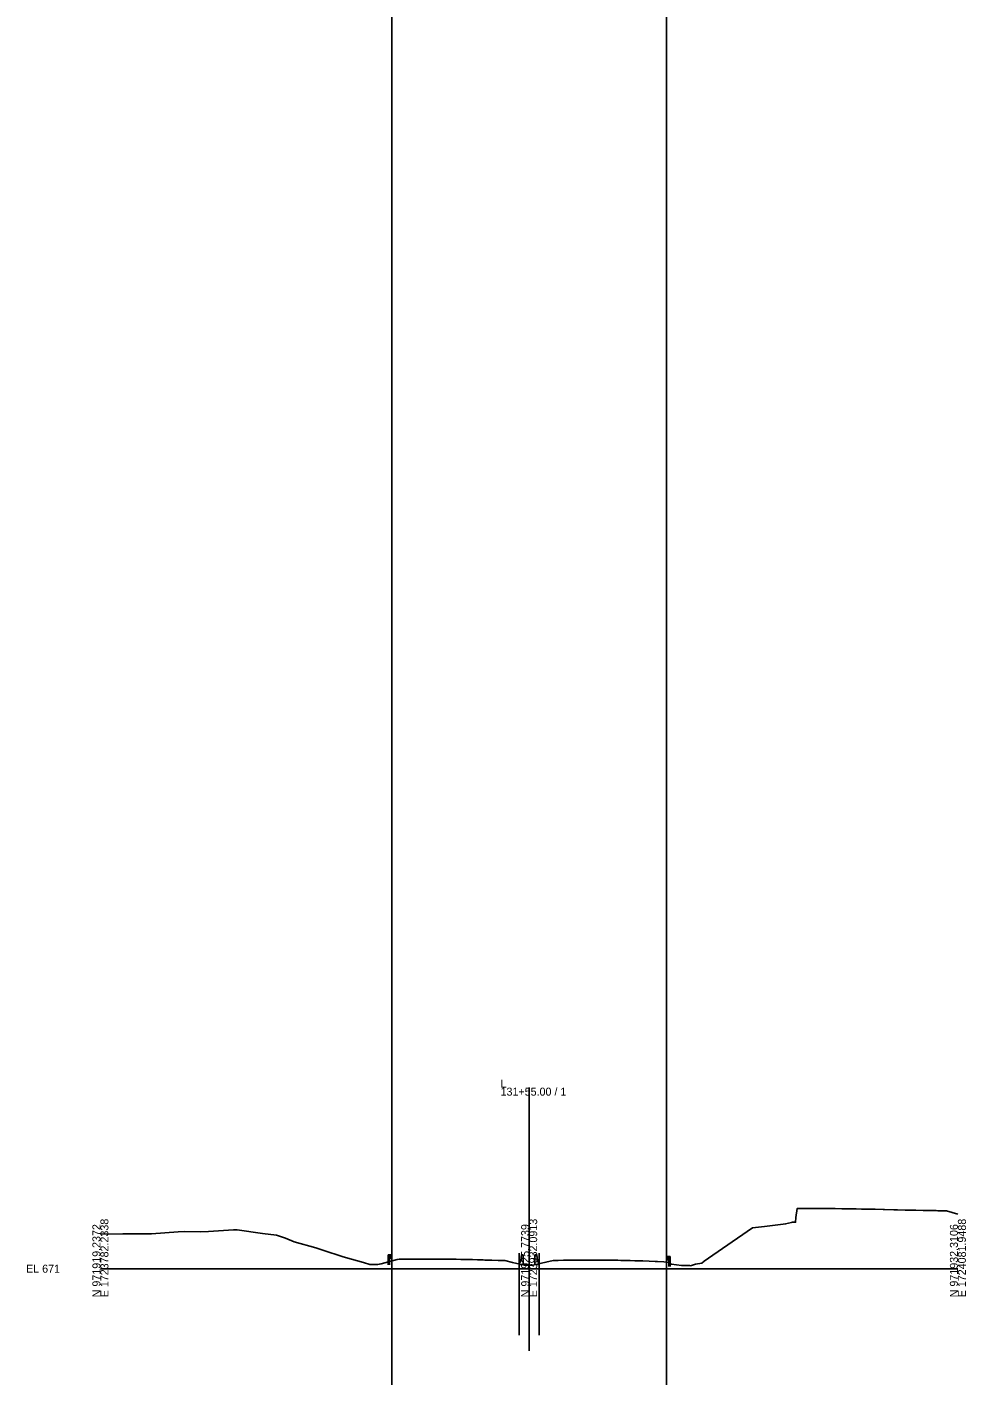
# Model space of a CAD drawing. Extents: x -26 to 303, y -29 to 15026.
# Drawn here: x -25.7 to 302.8, y 4962.8 to 5434.6 of the extents above; entities that cross this region are included whole.
import ezdxf

# ---------------------------------------------------------------- set-up
doc = ezdxf.new("R2010")
doc.units = 0
for name, color, linetype in [('Exist Cross Section Cell', 7, 'Continuous'), ('Exist XS Center Line Elevation Label', 7, 'Continuous'), ('Exist XS Ground Line', 7, 'Continuous'), ('Scratch_Level_0', 7, 'Continuous'), ('Typical Guardrail CELL', 7, 'Continuous'), ('Typical Median Barrier CELL', 7, 'Continuous')]:
    doc.layers.add(name, color=color, linetype=linetype)

msp = doc.modelspace()

# ---------------------------------------------------------------- linework, layer by layer
at = {"layer": 'Exist Cross Section Cell'}
for p, q in [((150, 5000), (150, 5063.37)), ((0, 5000), (150, 5000)), ((150, 5000), (300, 5000))]:
    msp.add_line(p, q, dxfattribs=at)
at = {"layer": 'Exist XS Ground Line'}
msp.add_lwpolyline([(0, 5012.06), (7.79, 5012.2), (8.19, 5012.21), (17.84, 5012.21), (27.19, 5012.94), (29.54, 5013.02), (35.07, 5012.96), (37.81, 5012.97), (46.55, 5013.56), (47.82, 5013.61), (56.69, 5012.3), (61.57, 5011.74), (64.71, 5010.71), (67.84, 5009.46), (75.33, 5007.33), (77.85, 5006.51), (84.92, 5004.14), (87.86, 5003.33), (91.99, 5002.18), (94.31, 5001.47), (94.81, 5001.46), (97.04, 5001.53), (97.57, 5001.55), (98.19, 5001.7), (103.79, 5003.26), (104.55, 5003.29), (105.23, 5003.31), (106.97, 5003.37), (107.79, 5003.38), (109.49, 5003.39), (110.54, 5003.4), (111.24, 5003.4), (111.99, 5003.4), (113.03, 5003.38), (114.49, 5003.37), (115.85, 5003.37), (116.99, 5003.37), (118.25, 5003.35), (119.48, 5003.34), (120.82, 5003.32), (121.96, 5003.31), (122.6, 5003.3), (123.05, 5003.3), (123.71, 5003.3), (124.46, 5003.29), (126.05, 5003.26), (126.96, 5003.25), (128.69, 5003.21), (129.48, 5003.19), (130.21, 5003.17), (131.97, 5003.12), (133.9, 5003.06), (134.48, 5003.05), (134.86, 5003.03), (135.75, 5003.01), (136.97, 5002.96), (139.15, 5002.91), (139.46, 5002.9), (140.41, 5002.87), (141.54, 5002.83), (144.22, 5002.14), (148.28, 5001.29), (150.03, 5001.23), (151.31, 5001.3), (155.84, 5002.28), (158.36, 5002.87), (158.74, 5002.87), (159.53, 5002.89), (160.09, 5002.91), (161.98, 5002.96), (162.8, 5002.98), (164.48, 5003.02), (165.97, 5003.02), (167.03, 5003.02), (168.6, 5003.03), (169.54, 5003.04), (170.58, 5003.03), (172.05, 5003.03), (173.39, 5003.03), (174.55, 5003.03), (176.38, 5003.02), (177.27, 5003.01), (177.9, 5003), (179.53, 5002.97), (180.99, 5002.94), (182.02, 5002.92), (183.63, 5002.88), (184.51, 5002.86), (185.33, 5002.84), (187.02, 5002.8), (189.09, 5002.76), (189.46, 5002.75), (189.8, 5002.73), (192.04, 5002.64), (194.14, 5002.54), (194.55, 5002.52), (194.93, 5002.5), (197.13, 5002.38), (197.79, 5002.34), (197.93, 5002.26), (198.69, 5002.14), (199.39, 5001.74), (199.74, 5001.64), (203.34, 5001.07), (206.09, 5001.07), (206.5, 5001.01), (208.24, 5001.63), (210.46, 5001.99), (211.26, 5002.66), (212.76, 5003.75), (217.64, 5007.05), (228.12, 5014.31), (232.38, 5014.82), (238.89, 5015.59), (239.72, 5015.68), (241.74, 5016.14), (241.84, 5016.28), (242.59, 5016.26), (243.21, 5016.26), (243.25, 5017.92), (243.81, 5021.12), (244.66, 5021.12), (247.05, 5021.09), (249.44, 5021.08), (251.53, 5021.06), (251.85, 5021.06), (254.36, 5021.05), (257.09, 5021.03), (259.37, 5021.01), (259.72, 5021), (261.86, 5020.97), (263.83, 5020.94), (264.36, 5020.93), (266.23, 5020.89), (266.86, 5020.88), (268.96, 5020.83), (270.46, 5020.81), (271.1, 5020.79), (273.82, 5020.7), (274.26, 5020.7), (277.57, 5020.59), (278.89, 5020.6), (281.49, 5020.54), (283.36, 5020.52), (285.24, 5020.49), (287.88, 5020.42), (289.2, 5020.39), (292.43, 5020.32), (292.96, 5020.31), (296, 5020.31), (300, 5019.07)], dxfattribs=at)
at = {"layer": 'Scratch_Level_0'}
for p, q in [((102, 15009.56), (102, -28.7)), ((198, 15009.56), (198, -28.7)), ((146.46, 5005.5), (146.46, 4976.8)), ((153.54, 5005.5), (153.54, 4976.8)), ((150, 5000), (150, 4971.3)), ((150, 5000), (150, 4971.3))]:
    msp.add_line(p, q, dxfattribs=at)
at = {"layer": 'Typical Guardrail CELL'}
for p, q in [((101.18, 5004.88), (100.68, 5004.88)), ((100.68, 5004.88), (100.68, 5002.39)), ((101.18, 5002.39), (100.68, 5002.39)), ((100.68, 5002.39), (100.68, 5001.38)), ((101.18, 5004.88), (101.18, 5002.39)), ((101.18, 5004.88), (101.68, 5004.88)), ((101.18, 5003.72), (101.68, 5003.72)), ((101.18, 5002.39), (101.18, 5001.38)), ((101.68, 5004.88), (101.68, 5003.72)), ((101.68, 5004.88), (101.97, 5004.67)), ((101.68, 5004.34), (101.97, 5004.54)), ((101.68, 5004.3), (101.68, 5004.34)), ((101.68, 5004.3), (101.68, 5004.25)), ((101.68, 5004.25), (101.97, 5004.05)), ((101.68, 5003.72), (101.97, 5003.92)), ((198.32, 5004.27), (198.03, 5004.07)), ((198.32, 5003.74), (198.03, 5003.94)), ((198.32, 5003.64), (198.03, 5003.44)), ((198.32, 5003.11), (198.03, 5003.31)), ((198.82, 5004.27), (198.32, 5004.27)), ((198.32, 5004.27), (198.32, 5003.11)), ((198.32, 5003.69), (198.32, 5003.74)), ((198.32, 5003.69), (198.32, 5003.64)), ((198.82, 5003.11), (198.32, 5003.11)), ((198.82, 5004.27), (198.82, 5001.78)), ((198.82, 5004.27), (199.32, 5004.27)), ((198.82, 5001.78), (199.32, 5001.78)), ((198.82, 5001.78), (198.82, 5000.78)), ((199.32, 5004.27), (199.32, 5001.78)), ((199.32, 5001.78), (199.32, 5000.78))]:
    msp.add_line(p, q, dxfattribs=at)
for centre, start, end in [((101.92, 5004.61), 304.9888, 54.997), ((101.92, 5003.98), 304.9634, 54.9941), ((198.08, 5004), 125.003, 235.0112), ((198.08, 5003.38), 125.0059, 235.0366)]:
    msp.add_arc(centre, 0.0776, start, end, dxfattribs=at)
at = {"layer": 'Typical Median Barrier CELL'}
for p, q in [((146.46, 5001.87), (146.92, 5002.53)), ((146.46, 5001.46), (146.46, 5001.87)), ((147.96, 5001.46), (146.46, 5001.46)), ((147.07, 5002.92), (147.29, 5004.87)), ((147.29, 5004.87), (147.96, 5004.87)), ((147.96, 5004.87), (147.96, 5001.46)), ((152.71, 5004.87), (152.04, 5004.87)), ((152.04, 5004.87), (152.04, 5001.46)), ((152.04, 5001.46), (153.54, 5001.46)), ((152.93, 5002.92), (152.71, 5004.87)), ((153.54, 5001.87), (153.08, 5002.53)), ((153.54, 5001.46), (153.54, 5001.87))]:
    msp.add_line(p, q, dxfattribs=at)
for centre, start, end in [((146.24, 5003.01), 325.0039, 353.9447), ((153.76, 5003.01), 186.0553, 214.9961)]:
    msp.add_arc(centre, 0.833, start, end, dxfattribs=at)

# ---------------------------------------------------------------- texts
at = {"layer": 'Exist Cross Section Cell'}
for s, p in [('131+55.00 / 1', (140, 5060.57)), ('L', (140, 5063.37)), ('EL 671', (-26, 4998.6))]:
    msp.add_text(s, height=2.8, dxfattribs=at).set_placement(p)
for s, p in [('N 971919.2372', (0, 4990)), ('E 1723782.2338', (2.8, 4990)), ('N 971925.7739', (150, 4990)), ('E 1723932.0913', (152.8, 4990)), ('N 971932.3106', (300, 4990)), ('E 1724081.9488', (302.8, 4990))]:
    msp.add_text(s, height=2.8, rotation=90, dxfattribs=at).set_placement(p)
at = {"layer": 'Exist XS Center Line Elevation Label'}
msp.add_text('672.24', height=0.18, dxfattribs=at).set_placement((149.61, 5000.75))

doc.saveas('drawing.dxf')
